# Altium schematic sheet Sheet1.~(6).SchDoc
size A4; SheetNumber: 1; SheetTotal: 1
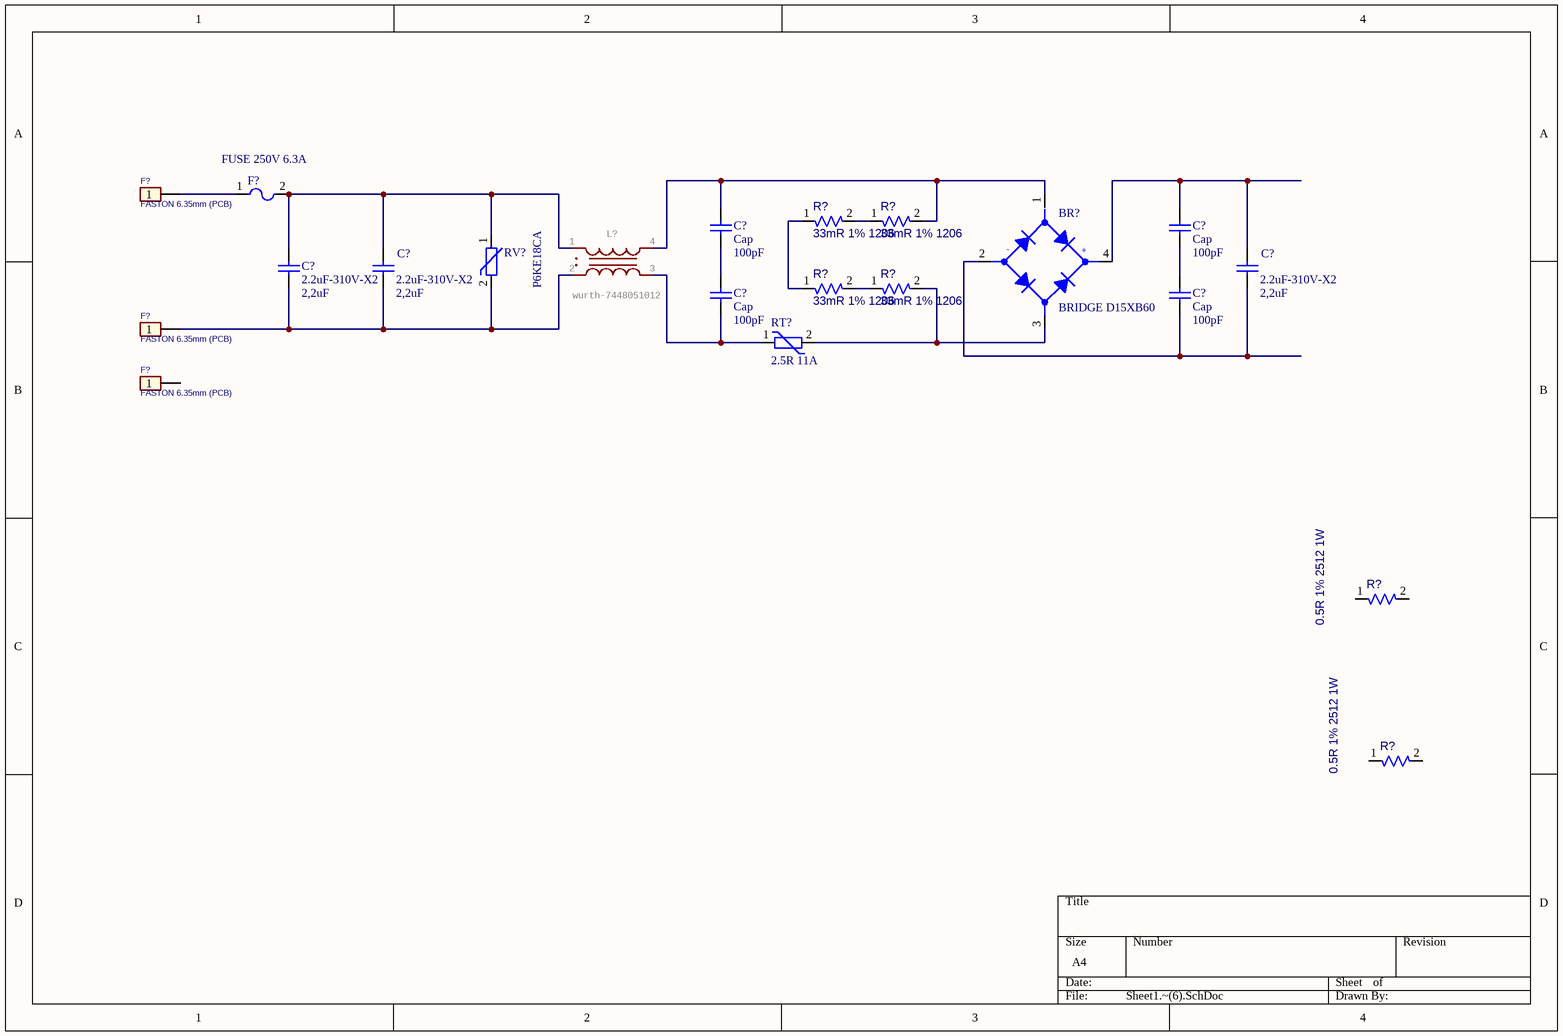
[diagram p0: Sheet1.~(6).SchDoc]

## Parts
(Parts that share a designator on the sheet are numbered #1, #2 ... from top to bottom, then left to right.)
BR?  BRIDGE D15XB60
C?#1  Cap  value 100pF  [RAD-0.3]
C?#2  Cap  value 100pF  [RAD-0.3]
C?#3  2.2uF-310V-X2  value 2,2uF
C?#4  2.2uF-310V-X2  value 2,2uF
C?#5  2.2uF-310V-X2  value 2,2uF
C?#6  Cap  value 100pF  [RAD-0.3]
C?#7  Cap  value 100pF  [RAD-0.3]
F?#1  FASTON 6.35mm (PCB)  [FASTON_M_PCB_6.35x0.81]
F?#2  FUSE 250V 6.3A  [BEL_FUSE_0697A6300-01]
F?#3  FASTON 6.35mm (PCB)  [FASTON_M_PCB_6.35x0.81]
F?#4  FASTON 6.35mm (PCB)  [FASTON_M_PCB_6.35x0.81]
L?  wurth-7448051012  [WE-CMBNC_XL_7448051012]
R?#1  33mR 1% 1206  [1206_UP_RES]
R?#2  33mR 1% 1206  [1206_UP_RES]
R?#3  33mR 1% 1206  [1206_UP_RES]
R?#4  33mR 1% 1206  [1206_UP_RES]
R?#5  0.5R 1% 2512 1W  [2512_up]
R?#6  0.5R 1% 2512 1W  [2512_up]
RT?  2.5R 11A
RV?  P6KE18CA  [DO15]

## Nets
NetBR?_1: BR?.1(AC1) C?#1.2 L?.4 R?#2.2
NetBR?_2: BR?.2(-DC) C?#5.2 C?#7.1
NetBR?_3: BR?.3(AC2) R?#4.2 RT?.2
NetBR?_4: BR?.4(+DC) C?#2.2 C?#5.1
NetC?#1_1: C?#1.1 C?#6.2
NetC?#2_1: C?#2.1 C?#7.2
NetC?#3_1: C?#3.1 C?#4.1 F?#2.2 L?.1 RV?.1
NetC?#3_2: C?#3.2 C?#4.2 F?#3.1 L?.2 RV?.2
NetC?#6_1: C?#6.1 L?.3 RT?.1
NetF?#1_1: F?#1.1 F?#2.1
NetR?#1_1: R?#1.1 R?#3.1
NetR?#1_2: R?#1.2 R?#2.1
NetR?#3_2: R?#3.2 R?#4.1

Not connected (* = marked no-connect by the designer): F?#4 1; R?#5 1 2; R?#6 1 2

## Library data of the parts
BR? = BRIDGE_D15XB60_15A_600V: BRIDGE D15XB60 15A 600V; Costo: 0; Aggiornato: NO
C?#1 C?#2 C?#6 C?#7 = Cap: Capacitor
C?#3-C?#5 = Cap: 2.2uF-310V-X2  VISHAY F339M/52231MIM2T0
F?#1 F?#3 F?#4 = FASTON_M_PCB_6.35mm: FASTON M PCB 6.35mm; Hpcode: FASTMASCSTAMP; Costo: 0,01; Aggiornato: s; ContoLavoro: 0
F?#2 = FUSE_250V_6.3A_T_BEL_FUSE_0697A6300-01: FUSE 250Vac 6.3A Time Delay BEL FUSE 0697A6300-01; Costo: 0,26; Aggiornato: S; ContoLavoro: 0
L? = WE-CMBNC_XL_7448051012: GateName_1: G$1; IR: 10A; RDC: 15mOhm; VR: 250  V (AC); VT: 1500  V (AC)
R?#1-R?#4 = R_0.33_1%_1206: 33mR 1% 1206 SMD RESISTOR; Value: 0.033; Costo: 0,17; Aggiornato: s; ContoLavoro: 0
R?#5 R?#6 = R_0.5R_1%_2512: 0.5R 1% 2512 1W SMD RESISTOR; Costo: 0,40; Value: 0.5; Aggiornato: s; ContoLavoro: 0
RT? = RT_2.5R_10A: NTC 2.5R 11A  TDK B57364S0259M0 21x7; Costo: 0; Aggiornato: NO
RV? = VARISTOR: VARISTORE VISHAY P6KE18CA-E3/54 ALT:RS 699-7972; Costo: 0,155; Aggiornato: NO; ContoLavoro: 0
